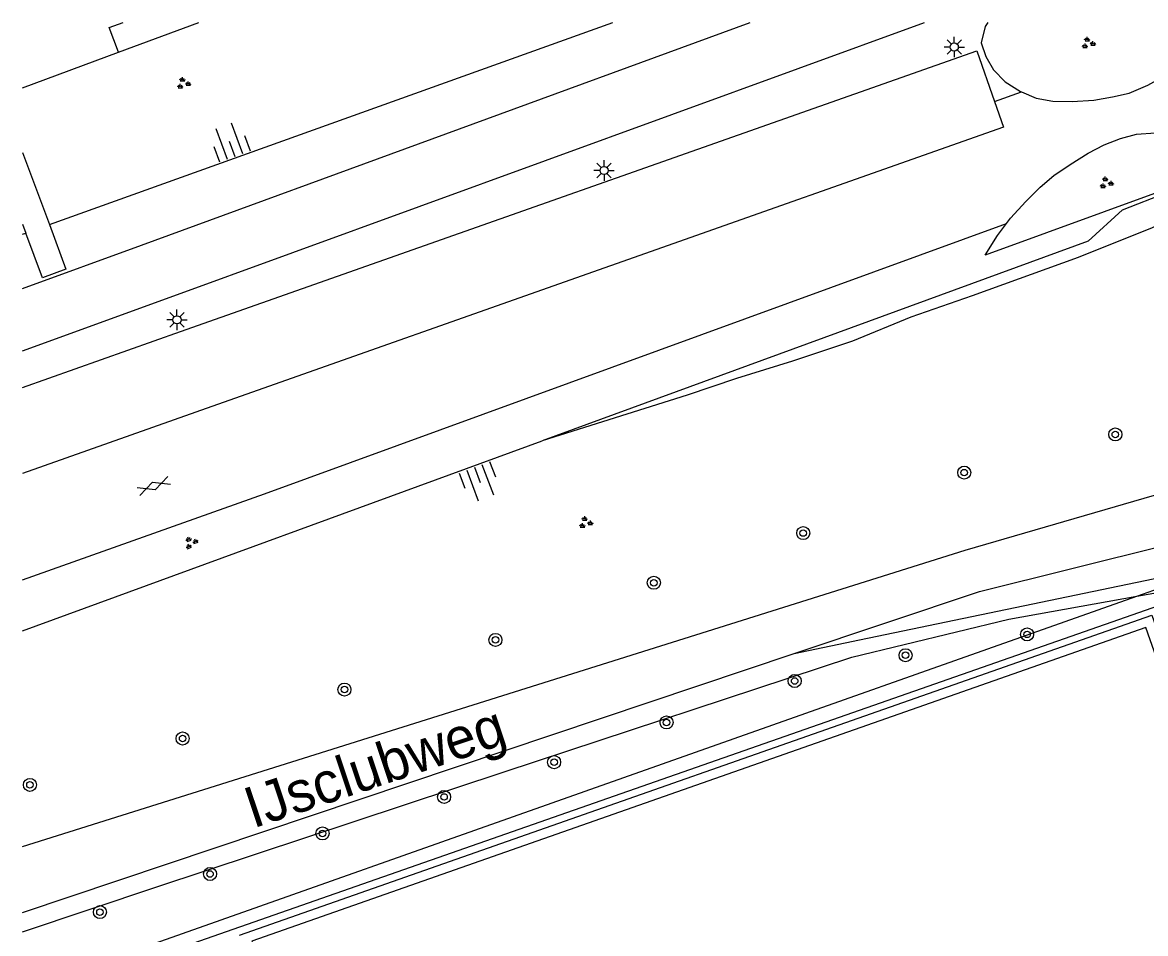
# Model space of a CAD drawing. Extents: x 135990 to 139000, y 393500 to 396000.
# Drawn here: x 136000 to 136068.8, y 395944.2 to 396000 of the extents above; entities that cross this region are included whole.
import ezdxf

# ---------------------------------------------------------------- set-up
doc = ezdxf.new("R2010")
doc.units = 0
for name, color, linetype in [('gg-afsc-hekwerk', 7, 'Continuous'), ('gg-anno-openbare ruimte label', 7, 'Continuous'), ('gg-knt-BGT kruinlijn', 7, 'Continuous'), ('gg-knt-bovenkant onderkant talud', 7, 'Continuous'), ('gg-knt-onverhard', 7, 'Continuous'), ('gg-knt-trap', 7, 'Continuous'), ('gg-knt-verharding', 7, 'Continuous'), ('gt-grn-groengrens', 7, 'Continuous'), ('gt-symb-boom', 7, 'Continuous'), ('gt-symb-gesloten verharding', 7, 'Continuous'), ('gt-symb-groenvak', 7, 'Continuous'), ('gt-symb-lichtmast', 7, 'Continuous'), ('gt-symb-talud symbool', 7, 'Continuous')]:
    doc.layers.add(name, color=color, linetype=linetype)

# ---------------------------------------------------------------- blocks, each defined once
blk = doc.blocks.new('gt0-GRVAK')
at = {"layer": 'gt-symb-groenvak'}
for p, q in [((-0.11, 0.189), (-0.228, 0.24)), ((-0.182, 0.153), (0.088, 0.153)), ((-0.091, 0.211), (-0.156, 0.322)), ((-0.047, 0.214), (-0.047, 0.393)), ((-0.004, 0.211), (0.061, 0.322)), ((0.015, 0.189), (0.133, 0.24)), ((0.262, -0.052), (0.197, 0.059)), ((0.305, -0.049), (0.305, 0.13)), ((0.349, -0.052), (0.414, 0.059)), ((-0.245, -0.228), (-0.363, -0.177)), ((-0.318, -0.264), (-0.047, -0.264)), ((-0.226, -0.206), (-0.291, -0.095)), ((-0.183, -0.203), (-0.183, -0.024)), ((-0.139, -0.206), (-0.074, -0.095)), ((-0.12, -0.228), (-0.002, -0.177)), ((0.243, -0.074), (0.125, -0.023)), ((0.17, -0.11), (0.441, -0.11)), ((0.368, -0.074), (0.486, -0.023))]:
    blk.add_line(p, q, dxfattribs=at)
blk = doc.blocks.new('gt0-LMAST')
at = {"layer": 'gt-symb-lichtmast'}
for p, q in [((-0.182, 0.173), (-0.447, 0.438)), ((-0.005, 0.246), (-0.005, 0.621)), ((0.172, 0.173), (0.437, 0.438)), ((-0.255, -0.004), (-0.63, -0.004)), ((-0.182, -0.181), (-0.447, -0.446)), ((-0.005, -0.254), (-0.005, -0.629)), ((0.437, -0.446), (0.172, -0.181)), ((0.245, -0.004), (0.62, -0.004))]:
    blk.add_line(p, q, dxfattribs=at)
blk.add_circle((-0.005, -0.004), 0.25, dxfattribs=at)
blk = doc.blocks.new('gt0-BOOM')
at = {"layer": 'gt-symb-boom'}
for radius in [0.4, 0.2]:
    blk.add_circle((0, 0), radius, dxfattribs=at)
blk = doc.blocks.new('gt0-GESVH1')
at = {"layer": 'gt-symb-gesloten verharding'}
for p, q in [((-0.992, -0.261), (0.008, 0.239)), ((0.008, -0.261), (-0.992, 0.239)), ((0.008, 0.239), (1.008, -0.261)), ((1.008, 0.239), (0.008, -0.261))]:
    blk.add_line(p, q, dxfattribs=at)
blk = doc.blocks.new('gt0-TALUD_1')
at = {"layer": 'gt-symb-talud symbool'}
for p, q in [((-1, -1), (-1, 0)), ((-0.5, -2), (-0.5, 0)), ((0, -1), (0, 0)), ((0.5, -2), (0.5, 0)), ((1, -1), (1, 0))]:
    blk.add_line(p, q, dxfattribs=at)

msp = doc.modelspace()

# ---------------------------------------------------------------- linework, layer by layer
at = {"layer": 'gg-afsc-hekwerk'}
msp.add_line((136068.261, 395964.861), (136071.685, 395965.472), dxfattribs=at)
for points in [[(136000, 395944.309), (136008.233, 395947.07), (136029.518, 395954.105), (136050.816, 395961.119), (136060.426, 395963.463), (136068.261, 395964.861)], [(136000, 395944.309), (136008.233, 395947.07), (136029.518, 395954.105), (136050.816, 395961.119), (136060.426, 395963.463), (136068.261, 395964.861)], [(136013.297, 395944.096), (136069.189, 395963.707), (136073.735, 395950.784), (136073.804, 395950.808), (136075.049, 395947.25), (136074.985, 395947.228), (136077.216, 395940.886), (136078.717, 395941.38), (136080.519, 395936.204), (136079.048, 395935.657), (136082.477, 395925.857), (136082.504, 395925.866)]]:
    msp.add_lwpolyline(points, dxfattribs=at)
at = {"layer": 'gg-knt-BGT kruinlijn'}
for p, q in [((136001.647, 395987.625), (136036.16, 396000)), ((136067.391, 395988.52), (136070.105, 395989.582)), ((136000, 395987.035), (136000.199, 395987.106)), ((136000, 395962.738), (136031.829, 395974.372))]:
    msp.add_line(p, q, dxfattribs=at)
msp.add_lwpolyline([(136067.391, 395988.52), (136065.281, 395986.6), (136031.829, 395974.372)], dxfattribs=at)
at = {"layer": 'gg-knt-bovenkant onderkant talud'}
for p, q in [((136051.282, 395962.185), (136072.97, 395966.702)), ((136047.279, 395961.351), (136051.282, 395962.185))]:
    msp.add_line(p, q, dxfattribs=at)
at = {"layer": 'gg-knt-onverhard'}
msp.add_line((136000, 395945.49), (136047.279, 395961.351), dxfattribs=at)
for points in [[(136000, 395949.531), (136057.751, 395967.68), (136069.339, 395971.05)], [(136047.279, 395961.351), (136058.631, 395965.16), (136070.013, 395967.992)]]:
    msp.add_lwpolyline(points, dxfattribs=at)
at = {"layer": 'gg-knt-trap'}
for p, q in [((136000, 395992.039), (136001.647, 395987.625)), ((136000, 395987.639), (136000.199, 395987.106))]:
    msp.add_line(p, q, dxfattribs=at)
msp.add_lwpolyline([(136001.647, 395987.625), (136002.665, 395984.897), (136001.226, 395984.355), (136000.199, 395987.106)], dxfattribs=at)
at = {"layer": 'gg-knt-verharding'}
for p, q in [((136005.882, 395998.172), (136010.797, 396000)), ((136000, 395995.99), (136005.882, 395998.172)), ((136059.548, 395995.169), (136061.204, 395995.749))]:
    msp.add_line(p, q, dxfattribs=at)
for points in [[(136000, 395983.7), (136007.291, 395986.358), (136044.58, 396000)], [(136000, 395979.889), (136008.825, 395983.104), (136055.26, 396000)], [(136005.882, 395998.172), (136005.319, 395999.685), (136006.168, 396000)], [(136059.135, 396000), (136058.968, 395999.761), (136058.738, 395998.758), (136059.011, 395997.916), (136059.493, 395997.092), (136060.201, 395996.372), (136061.141, 395995.776), (136061.204, 395995.749)], [(136000, 395977.65), (136009.672, 395981.079), (136058.467, 395998.255), (136059.548, 395995.169)], [(136061.204, 395995.749), (136062.092, 395995.369), (136063.125, 395995.173), (136064.297, 395995.152), (136065.626, 395995.244), (136066.783, 395995.451), (136067.8, 395995.66), (136068.948, 395996.151), (136069.676, 395996.569), (136069.871, 395996.705)], [(136059.548, 395995.169), (136060.105, 395993.579), (136011.939, 395976.596), (136000, 395972.374)], [(136060.277, 395987.685), (136060.52, 395988.013), (136061.476, 395989.033), (136062.355, 395989.922), (136063.183, 395990.624), (136064.176, 395991.311), (136065.287, 395992.001), (136066.258, 395992.504), (136067.26, 395992.894), (136068.252, 395993.155), (136069.405, 395993.237), (136070.39, 395993.068), (136071.336, 395992.494)], [(136070.024, 395989.77), (136058.97, 395985.754), (136059.735, 395986.953), (136060.277, 395987.685)], [(136000, 395965.858), (136014.819, 395971.13), (136060.277, 395987.685)], [(136046.773, 395850.912), (136101.471, 395870.164), (136068.815, 395962.949), (136014.049, 395943.734), (136046.773, 395850.912)]]:
    msp.add_lwpolyline(points, dxfattribs=at)
at = {"layer": 'gt-grn-groengrens'}
for p, q in [((136068.261, 395964.861), (136071.503, 395966.006)), ((136000, 395940.753), (136068.261, 395964.861))]:
    msp.add_line(p, q, dxfattribs=at)
for points in [[(136070.461, 395988.931), (136070.453, 395988.027), (136069.197, 395987.42), (136064.673, 395985.596), (136058.189, 395983.265), (136054.417, 395981.947), (136050.843, 395980.477), (136047.172, 395979.26), (136043.75, 395978.194), (136040.73, 395977.179), (136031.829, 395974.372)], [(136000, 395939.952), (136070.907, 395964.744), (136077.317, 395946.013)]]:
    msp.add_lwpolyline(points, dxfattribs=at)

# ---------------------------------------------------------------- block references
at = {"layer": 'gt-symb-boom'}
for p in [(136066.949, 395974.768), (136057.692, 395972.429), (136047.832, 395968.729), (136038.679, 395965.686), (136028.975, 395962.187), (136061.542, 395962.524), (136054.097, 395961.247), (136047.305, 395959.669), (136019.723, 395959.144), (136039.457, 395957.132), (136009.813, 395956.149), (136032.567, 395954.698), (136000.46, 395953.307), (136025.827, 395952.567), (136018.38, 395950.333), (136011.49, 395947.849), (136004.747, 395945.516)]:
    msp.add_blockref('gt0-BOOM', p, dxfattribs=at)
at = {"layer": 'gt-symb-gesloten verharding', "rotation": 20.301249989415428}
msp.add_blockref('gt0-GESVH1', (136008.039, 395971.617), dxfattribs=at)
at = {"layer": 'gt-symb-groenvak'}
for p in [(136065.275, 395998.726), (136009.853, 395996.264), (136066.382, 395990.164), (136034.488, 395969.362)]:
    msp.add_blockref('gt0-GRVAK', p, dxfattribs=at)
at = {"layer": 'gt-symb-groenvak', "rotation": 19.57672556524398}
msp.add_blockref('gt0-GRVAK', (136010.308, 395968.128), dxfattribs=at)
at = {"layer": 'gt-symb-lichtmast'}
for p in [(136057.086, 395998.498), (136035.636, 395990.936), (136009.471, 395981.792)]:
    msp.add_blockref('gt0-LMAST', p, dxfattribs=at)
at = {"layer": 'gt-symb-talud symbool'}
for p, xscale, yscale, rotation in [((136013.003, 395991.797), 1.0002009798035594, 1.0002009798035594, -160.18818811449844), ((136027.703, 395972.737), 1.0003524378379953, 1.0003524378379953, 20.663302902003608)]:
    msp.add_blockref('gt0-TALUD_1', p, dxfattribs=dict(at, xscale=xscale, yscale=yscale, rotation=rotation))

# ---------------------------------------------------------------- texts
at = {"layer": 'gg-anno-openbare ruimte label'}
msp.add_text('IJsclubweg', height=2.5, rotation=18.5, dxfattribs=at).set_placement((136014.129, 395950.631))

doc.saveas('drawing.dxf')
